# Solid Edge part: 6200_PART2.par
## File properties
Author: PARTuser1
Template: Normal.par
Last saved by: Francesco
Revision: 3
Application: Solid Edge
Material: Acciaio
Stile della faccia: Acciaio
Stile di riempimento: ANSI32(Acciaio)
Stile virtuale: Acciaio lavorato a macchina
Coef. of Thermal Exp: 0.0
Thermal Conductivity: 32.0
Specific Heat: 481.0
Modulus of Elasticity: 199947953000.0
Poisson's Ratio: 0.29
Yield Stress: 262000766.0
Ultimate Stress: 358527364.0
Elongation: 0.0
Tipo di contenuto documento: 0
Density: 7833,000 kg/m^3
Accuracy: 0,990
CADENASNORM: 6200_PART2
CADENAS_NB: 6200_PART2
CADENAS_NN: _PART2
CADENAS_NBSYN: 6200_PART2
CADENAS_LINA: 6200_PART2
CADENAS_Z: 8.000
CADENAS_Y0W2: 9.239
CADENAS_R0N1: 0.000
CADENAS_DOUT: 30.000
CADENAS_YI: 8.500
CADENAS_D1ICOS: 23.200
CADENAS_YE: 11.600
CADENAS_Y0I: 10.000
CADENAS_D2: 24.800
CADENAS_D1: 23.200
CADENAS_Y0E: 10.000
CADENAS_X0I: 4.500
CADENAS_BN1: 0.000
CADENAS_CE: 0.000
CADENAS_R2I: 0.200
CADENAS_RWB: 2.381
CADENAS_X0E: 4.500
CADENAS_R2E: 0.200
CADENAS_Z0W2: 3.827
CADENAS_RI: 2.381
CADENAS_X0WB: 4.500
CADENAS_BICOS: 0.000
CADENAS_HIS1: 0.000
CADENAS_RE: 2.381
CADENAS_XI: 0.000
CADENAS_RC: 0.000
CADENAS_XE: 0.000
CADENAS_HE2: 2.600
CADENAS_X0W2: 4.500
CADENAS_BOREDIAMETER: 10.000
CADENAS_RSG: 0.283
CADENAS_BI: 9.000
CADENAS_HN1: 0.000
CADENAS_HI: 3.500
CADENAS_BE: 9.000
CADENAS_R1I: 0.600
CADENAS_HH: 0.000
CADENAS_PRODUCTID: 1050010200.000
CADENAS_HE: 3.400
CADENAS_BEARINGWIDTH: 9.000
CADENAS_R1E: 0.600
CADENAS_BICOS1: 0.000
CADENAS_HICOS: 0.000
CADENAS_DKI: 17.000
CADENAS_Y0WB: 10.000
CADENAS_comment: design:dgbb1; version:5000.3; lang:it; selectedUnitParts:000000; action:download; skf2d3daction.jsp version:2008-03-06; getRequestURI:/skf/skf3dnew/skf2d3daction.jsp
CADENAS_KT: DUMMY
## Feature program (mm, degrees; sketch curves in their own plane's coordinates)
sketch for "unnamed RevolvedProtrusion 1" plane through (0, 0, 0) normal (0, 0, 1) x-axis (1, 0, 0)
  line (0, 14.4) -> (0, 12.4)
  line (0, 12.4) -> (0.2201, 12.4)
  arc centre (0.5031, 12.4) radius 0.283 from (0.2201, 12.4) to (0.7861, 12.4) cw
  line (0.7861, 12.4) -> (0.9272, 11.6)
  line (0.9272, 11.6) -> (2.7367, 11.6)
  arc centre (4.5, 10) radius 2.381 from (2.7367, 11.6) to (6.2633, 11.6) cw
  line (6.2633, 11.6) -> (8.0728, 11.6)
  line (8.0728, 11.6) -> (8.2139, 12.4)
  arc centre (8.4969, 12.4) radius 0.283 from (8.2139, 12.4) to (8.7799, 12.4) cw
  line (8.7799, 12.4) -> (9, 12.4)
  line (9, 12.4) -> (9, 14.4)
  arc centre (8.4, 14.4) radius 0.6 from (9, 14.4) to (8.4, 15) ccw
  line (8.4, 15) -> (0.6, 15)
  arc centre (0.6, 14.4) radius 0.6 from (0.6, 15) to (0, 14.4) ccw
revolve "unnamed RevolvedProtrusion 1" add finite 360 deg about sketch line (8.4, 0) -> (0.6, 0)
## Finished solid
Body 1: solid body, 14 faces, 14 edges, 0 vertices.
  Faces by surface: cylinder 5, torus 5, cone 2, plane 2
  Edges by curve: circle 14
Bounding box of the edges (mm; curved faces can reach further): 9.000 x 30.000 x 30.000, from (0, -15, -15) to (9, 15, 15).
Cylindrical faces by radius (mm): R11.6 x2, R12.4 x2, R15 x1
Conical faces (half-angle, radius in mm at the cone's reference point): 80 deg R11.6 x1, 80 deg R12.4 x1
Toroidal faces (ring radius, tube radius in mm): R10 r2.381 x1, R12.4 r0.283 x2, R14.4 r0.6 x2
Planar faces by outward normal: +x 1, -x 1
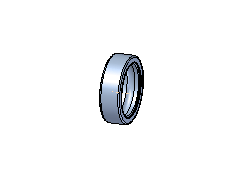
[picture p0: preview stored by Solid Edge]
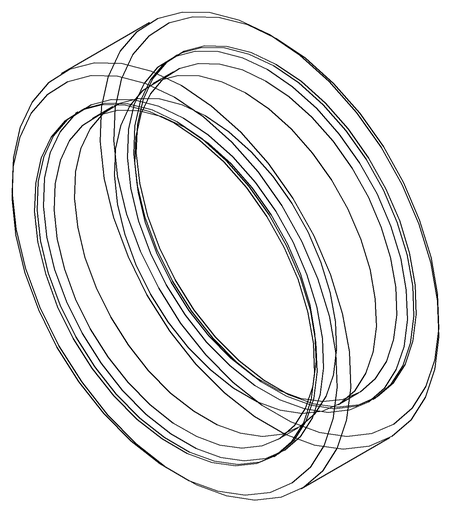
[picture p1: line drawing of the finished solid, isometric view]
